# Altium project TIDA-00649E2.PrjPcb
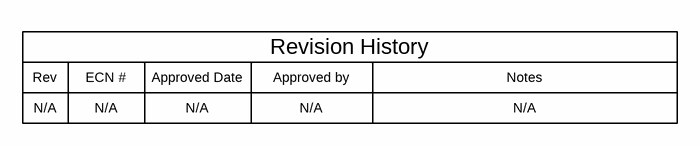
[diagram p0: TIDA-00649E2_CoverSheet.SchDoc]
TID: TIDA-00649; TechSupport: http://www.ti.com/support; SCH_Rev: E2; PRJ_Title: 4-20-mA Loop Energy Harvester Reference Design; PRJ_Number: TIDA-00649; PRJ_Engineer: GVN; PRJ_Customer: Public Release; PCB_Rev: E2; CopyrightYear: 2016
4 sheets, 121 parts. Net scope: flat (ports and power ports of the same name join across sheets).
Board file: TIDA-00649E2_PCB.PcbDoc
Sheets:
  TIDA-00649E2_CoverSheet.SchDoc
  TIDA-00649E2_DiodeVoltage.SchDoc
  TIDA-00649E2_EVM_Hardware.SchDoc
  TIDA-00649E2_Boost.SchDoc

## Sheet TIDA-00649E2_CoverSheet.SchDoc
size 431 x 279 mm; Date: Not shown in title block; ApprovedBy: Not shown in title block; CheckedBy: Not shown in title block; Author: Not shown in title block; CompanyName: Not shown in title block; Engineer: Not shown in title block; Organization: Not shown in title block; Address1: Not shown in title block; Address2: Not shown in title block; Address3: Not shown in title block; Address4: Not shown in title block; DocumentNumber: 1; Revision: E2; SheetNumber: 1; SheetTotal: 4; PageSetup: Record=PageOptions¦CenterHorizontal=True¦CenterVertical=True¦PrintScale=1.00¦XCorrection=1.00¦YCorrection=1.00¦PrintKind=0¦BorderSize=5000000¦LeftOffset=0¦BottomOffset=0¦Orientation=2¦PaperLength=1000¦PaperWidth=1000¦Scale=100¦PaperSource=15¦PrintQuality=600¦MediaType=1¦DitherType=10¦PaperKind=Letter¦PrintScaleMode=1

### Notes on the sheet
- Rev
- N/A
- ECN #
- Approved Date
- Approved by
- Revision History
- Notes

## Sheet TIDA-00649E2_DiodeVoltage.SchDoc: Diode Voltage
size 431 x 279 mm; Date: Not shown in title block; ApprovedBy: Not shown in title block; CheckedBy: Not shown in title block; Author: Not shown in title block; CompanyName: Not shown in title block; Engineer: Not shown in title block; Organization: Not shown in title block; Address1: Not shown in title block; Address2: Not shown in title block; Address3: Not shown in title block; Address4: Not shown in title block; DocumentNumber: 2; Revision: E2; SheetNumber: 2; SheetTotal: 4; PageSetup: Record=PageOptions¦CenterHorizontal=True¦CenterVertical=True¦PrintScale=0.95¦XCorrection=1.00¦YCorrection=1.00¦PrintKind=0¦BorderSize=5000000¦LeftOffset=0¦BottomOffset=0¦Orientation=2¦PaperLength=1000¦PaperWidth=1000¦Scale=100¦PaperSource=15¦PrintQuality=-3¦MediaType=1¦DitherType=10¦PrintScaleMode=1¦PaperKind=11x17¦PaperIndex=3
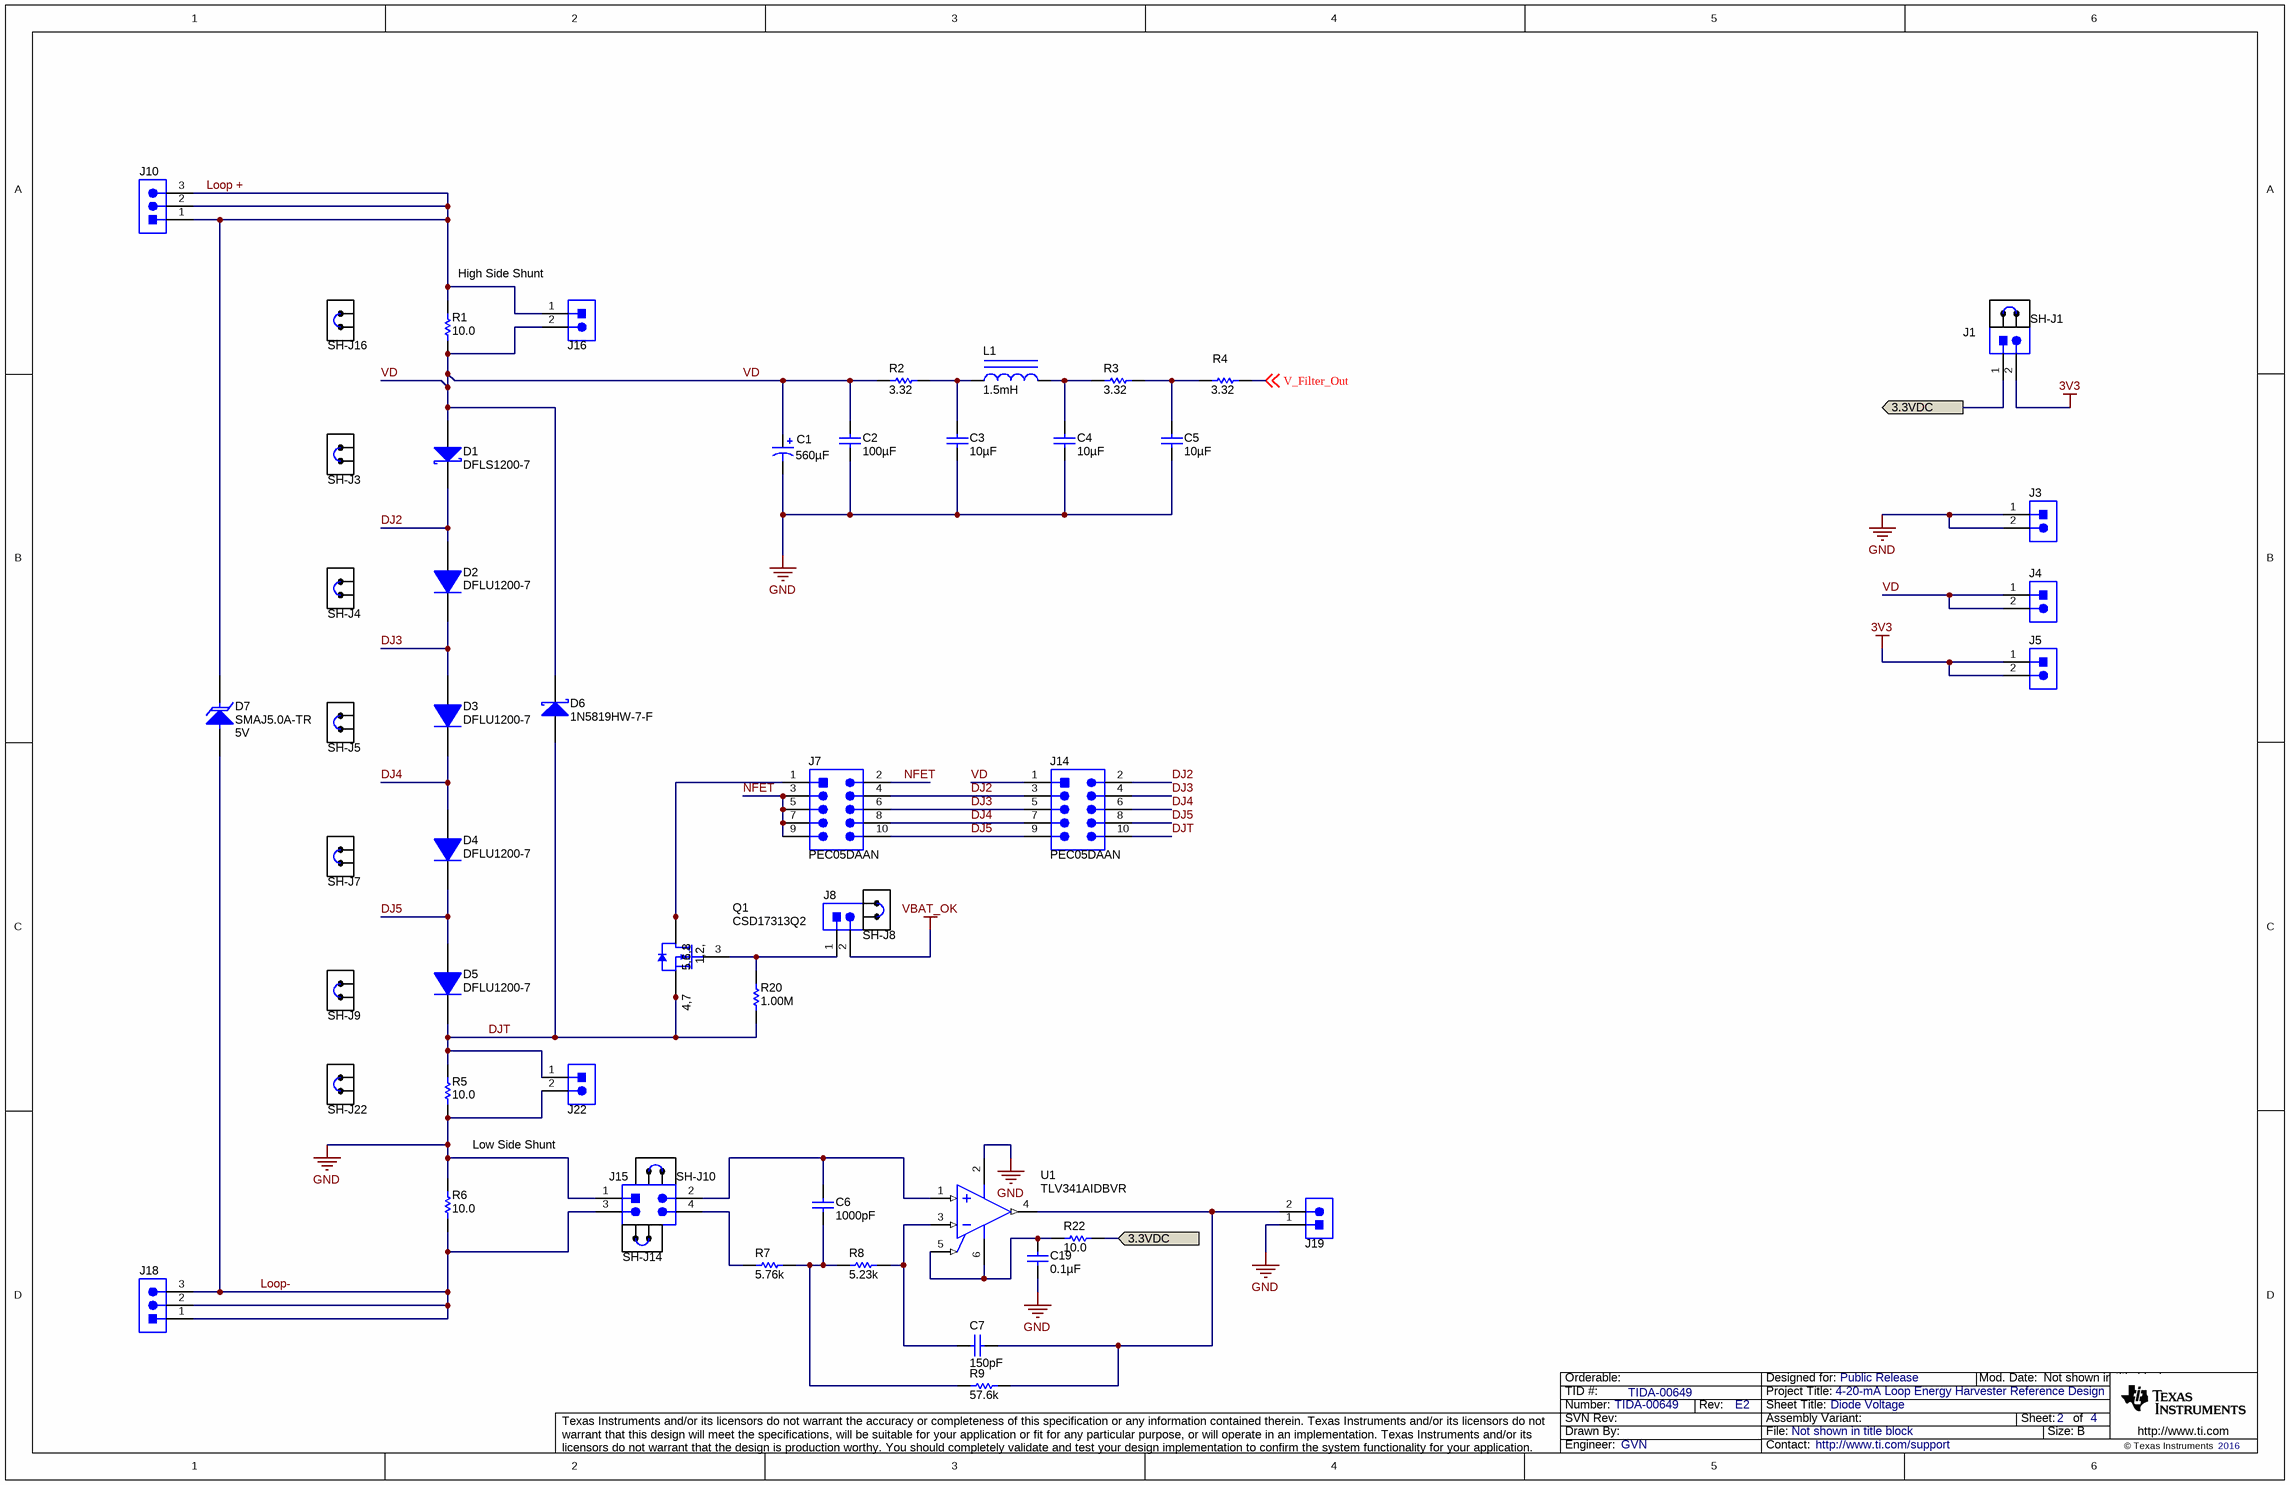
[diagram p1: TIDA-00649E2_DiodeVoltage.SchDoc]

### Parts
C1  ValueDisplayed: 560µF  [Panasonic_G]  (hidden comment: EEEFPE561UAP)
C2  ValueDisplayed: 100µF  [0805_HV]  (hidden comment: GRM21BR60J107M)
C3  ValueDisplayed: 10µF  [0805_HV]  (hidden comment: GRM21BR61A106KE19L)
C4  ValueDisplayed: 10µF  [0805_HV]  (hidden comment: GRM21BR61A106KE19L)
C5  ValueDisplayed: 10µF  [0805_HV]  (hidden comment: GRM21BR61A106KE19L)
C6  ValueDisplayed: 1000pF  [0603]  (hidden comment: C0603C102J5GAC)
C7  ValueDisplayed: 150pF  [0603]  (hidden comment: C0603C151J5GACTU)
C19  ValueDisplayed: 0.1µF  [0603]  (hidden comment: 885012206046)
D1  DFLS1200-7  [PowerDI123]
D2  DFLU1200-7  [PowerDI123]
D3  DFLU1200-7  [PowerDI123]
D4  DFLU1200-7  [PowerDI123]
D5  DFLU1200-7  [PowerDI123]
D6  1N5819HW-7-F  [SOD-123]
D7  SMAJ5.0A-TR  value 5V  [SMA]
J1  61300211121  [WURTH_61300211121]  (value not drawn)
J3  SSW-102-01-T-S  [Samtec_SSW-102-01-x-S]  (value not drawn)
J4  SSW-102-01-T-S  [Samtec_SSW-102-01-x-S]  (value not drawn)
J5  SSW-102-01-T-S  [Samtec_SSW-102-01-x-S]  (value not drawn)
J7  PEC05DAAN  [CONN_PEC05DAAN]
J8  61300211121  [WURTH_61300211121]  (value not drawn)
J10  61300311121  [WURTH_61300311121]  (value not drawn)
J14  PEC05DAAN  [CONN_PEC05DAAN]
J15  PBC02DAAN  [Sullins_PxC02DAAN]  (value not drawn)
J16  61300211121  [WURTH_61300211121]  (value not drawn)
J18  61300311121  [WURTH_61300311121]  (value not drawn)
J19  61300211121  [WURTH_61300211121]  (value not drawn)
J22  61300211121  [WURTH_61300211121]  (value not drawn)
L1  ValueDisplayed: 1.5mH  [SLF10145]  (hidden comment: SLF10145T-152MR22-PF)
Q1  CSD17313Q2  [DQK0006C]
R1  ValueDisplayed: 10.0  [1206]  (hidden comment: CRCW120610R0FKEA)
R2  ValueDisplayed: 3.32  [0402]  (hidden comment: CRCW04023R32FKED)
R3  ValueDisplayed: 3.32  [0402]  (hidden comment: CRCW04023R32FKED)
R4  ValueDisplayed: 3.32  [0402]  (hidden comment: CRCW04023R32FKED)
R5  ValueDisplayed: 10.0  [1206]  (hidden comment: CRCW120610R0FKEA)
R6  ValueDisplayed: 10.0  [1206]  (hidden comment: CRCW120610R0FKEA)
R7  ValueDisplayed: 5.76k  [0603]  (hidden comment: RC0603FR-075K76L)
R8  ValueDisplayed: 5.23k  [0603]  (hidden comment: CRCW06035K23FKEA)
R9  ValueDisplayed: 57.6k  [0603]  (hidden comment: CRCW060357K6FKEA)
R20  ValueDisplayed: 1.00M  [0603]  (hidden comment: CRCW06031M00FKEA)
R22  ValueDisplayed: 10.0  [0603]  (hidden comment: CRCW060310R0FKEA)
SH-J1  60900213421  [Wurth_60900213421]  (value not drawn)
SH-J3  60900213421  [Wurth_60900213421]  (value not drawn)
SH-J4  60900213421  [Wurth_60900213421]  (value not drawn)
SH-J5  60900213421  [Wurth_60900213421]  (value not drawn)
SH-J7  60900213421  [Wurth_60900213421]  (value not drawn)
SH-J8  60900213421  [Wurth_60900213421]  (value not drawn)
SH-J9  60900213421  [Wurth_60900213421]  (value not drawn)
SH-J10  60900213421  [Wurth_60900213421]  (value not drawn)
SH-J14  60900213421  [Wurth_60900213421]  (value not drawn)
SH-J16  60900213421  [Wurth_60900213421]  (value not drawn)
SH-J22  60900213421  [Wurth_60900213421]  (value not drawn)
U1  TLV341AIDBVR  [DBV0006A_N]

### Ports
3.3VDC

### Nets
3V3: J1.2 J5.1 J5.2
GND: C1.2(-) C2.2 C3.2 C4.2 C5.2 C19.1 J3.1 J3.2 J15.1 J19.1 J22.2 R5.1 R6.2 U1.2(GND)
VBAT_OK: J8.2
3.3VDC: J1.1 R22.2 ; port 3.3VDC
DJ2: D1.1(K) D2.2(A) J7.4 J14.2 J14.3
DJ3: D2.1(K) D3.2(A) J7.6 J14.4 J14.5
DJ4: D3.1(K) D4.2(A) J7.8 J14.6 J14.7
DJ5: D4.1(K) D5.2(A) J7.10 J14.8 J14.9
DJT: D5.1(K) D6.2(A) J14.10 J22.1 Q1.4(S) Q1.7(S) R5.2 R20.1
Loop +: D7.1(K) J10.1 J10.2 J10.3 J16.1 R1.2
Loop-: D7.2(A) J15.3 J18.1 J18.2 J18.3 R6.1
NFET: J7.2 J7.3 J7.5 J7.7 J7.9
V_Filter_Out: R4.2 ; off-sheet V_Filter_Out
VD: C1.1(+) C2.1 D1.2(A) D6.1(K) J4.1 J4.2 J14.1 J16.2 R1.1 R2.1
NetC3_1: C3.1 L1.1 R2.2
NetC4_1: C4.1 L1.2 R3.1
NetC5_1: C5.1 R3.2 R4.1
NetC6_1: C6.1 J15.2 U1.1(IN+)
NetC6_2: C6.2 R7.2 R8.1 R9.1
NetC7_1: C7.1 J19.2 R9.2 U1.4(OUT)
NetC7_2: C7.2 R8.2 U1.3(IN-)
NetC19_2: C19.2 R22.1 U1.5(~{SHDN}) U1.6(V+)
NetJ7_1: J7.1 Q1.1(D) Q1.2(D) Q1.5(D) Q1.6(D) Q1.8(D)
NetJ8_1: J8.1 Q1.3(G) R20.2
NetJ15_4: J15.4 R7.1

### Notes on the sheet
- High Side Shunt
- Low Side Shunt

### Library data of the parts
C1 = EEEFPE561UAP: CAP, AL, 560 µF, 25 V, +/- 20%, 0.08 ohm, AEC-Q200 Grade 2, SMD; Manufacturer: Panasonic; Polarized: Y; CompType: Capacitor; Value: 560uF; U/M: EA; Cap_F: 0.00056; Tolerance_%: 20; VDC_V: 25; Value2: 25V; ESR_ohm: 0.08; IRMS_A: 0.85; TaMin_C: -55; TaMax_C: 105; Cap_Case: 10x10.2mm; SizeAreaWB_mm2: 151.29; SizeArea_mm2: 106.09; SizeX_mm: 10.3; SizeZ_mm: 10.5; AEC Category: Q200; AEC Grade: 2
C2 = GRM21BR60J107M: CAP, CERM, 100 µF, 6.3 V, +/- 20%, X5R, 0805; Manufacturer: MuRata; Polarized: N; CompType: Capacitor; Value: 100uF; U/M: EA; Cap_F: 0.0001; Tolerance_%: 20; Value1: Unknown; VDC_V: 6.3; Value2: 6.3V; TaMin_C: -55; TaMax_C: 85; Cap_Case: 0805; SizeArea_mm2: 2.5; SizeAreaWB_mm2: 6.75; SizeX_mm: 2; SizeY_mm: 1.25; SizeZ_mm: 1.45; AEC Category: Q200
C3-C5 = GRM21BR61A106KE19L: CAP, CERM, 10 µF, 10 V, +/- 10%, X5R, 0805; Manufacturer: MuRata; Polarized: N; CompType: Capacitor; Value: 10uF; U/M: EA; Cap_F: 0.00001; Tolerance_%: 10; ESR_ohm: 0.002; Value1: 0.002 ohm; Value2: 10V; TaMin_C: -55; TaMax_C: 85; Cap_Case: 0805; SizeArea_mm2: 2.5; SizeAreaWB_mm2: 6.75; SizeX_mm: 2; SizeY_mm: 1.25; SizeZ_mm: 1.45; AEC Category: Q200
C6 = C0603C102J5GAC: CAP, CERM, 1000 pF, 50 V, +/- 5%, C0G/NP0, 0603; Manufacturer: Kemet; Polarized: N; CompType: Capacitor; Value: 1000pF; U/M: EA; Cap_F: 0.000000001; Tolerance_%: 5; Value1: Unknown; VDC_V: 50; Value2: 50V; TaMin_C: -55; TaMax_C: 125; SizeArea_mm2: 1.28; SizeAreaWB_mm2: 4.68; SizeX_mm: 1.6; SizeY_mm: 0.8; SizeZ_mm: 1; AEC Category: Q200
C7 = C0603C151J5GACTU: CAP, CERM, 150 pF, 50 V, +/- 5%, C0G/NP0, 0603; Manufacturer: Kemet; Polarized: N; CompType: Capacitor; Value: 150pF; U/M: EA; Cap_F: 0.00000000015; Tolerance_%: 5; Value1: Unknown; VDC_V: 50; Value2: 50V; TaMin_C: -55; TaMax_C: 125; SizeArea_mm2: 1.28; SizeAreaWB_mm2: 4.68; SizeX_mm: 1.6; SizeY_mm: 0.8; SizeZ_mm: 1; AEC Category: Q200
C19 = 885012206046: CAP, CERM, 0.1 µF, 16 V, +/- 10%, X7R, 0603; Manufacturer: Wurth Elektronik; Polarized: N; CompType: Capacitor; Value: 0.1uF; U/M: EA; Cap_F: 0.0000001; Tolerance_%: 10; Value1: Unknown; VDC_V: 16; Value2: 16V; TaMin_C: -55; TaMax_C: 125; SizeArea_mm2: 1.28; SizeAreaWB_mm2: 4.68; SizeX_mm: 1.6; SizeY_mm: 0.8; SizeZ_mm: 1; AEC Category: Q200
D1 = DFLS1200-7: Diode, Schottky, 200 V, 1 A, PowerDI123; Manufacturer: Diodes Inc.; U/M: EA; Vf_V: 0.85; Value: 200V; Value1: 1A; Value2: 0.85V; Io_A: 1; Vr_V: 200; TJmax_C: 175; RJC_CperW: 7; SizeAreaWB_mm2: 13.066; SizeArea_mm2: 6.586; SizeX_mm: 3.7; SizeY_mm: 1.78; SizeZ_mm: 0.98; AEC Category: Q101
D2-D5 = DFLU1200-7: Diode, Superfast Rectifier, 200 V, 1 A, AEC-Q101, PowerDI123; Manufacturer: Diodes Inc.; U/M: EA; Vf_V: 0.98; Value: 200V; Value1: 1A; Value2: 0.98V; Io_A: 1; Vr_V: 200; TJmax_C: 150; SizeAreaWB_mm2: 13.066; SizeArea_mm2: 6.586; SizeX_mm: 3.7; SizeY_mm: 1.78; AEC Category: Q101; AEC Qualified: Y
D6 = 1N5819HW-7-F: Diode, Schottky, 40 V, 1 A, SOD-123; Manufacturer: Diodes Inc.; U/M: EA; Vf_V: 0.45; Value: 40V; Value1: 1A; Value2: 0.45V; Io_A: 1; Vr_V: 40; TJmax_C: 125; SizeAreaWB_mm2: 13.095; SizeArea_mm2: 6.545; SizeX_mm: 3.85; SizeY_mm: 1.7; SizeZ_mm: 1.35; AEC Category: Q101
D7 = SMAJ5.0A-TR: Diode, TVS, Uni, 5 V, 13.4 Vc, SMA; Manufacturer: STMicroelectronics; U/M: EA; Vr_V: 5; Value1: W; RJA_CperW: 120; SizeAreaWB_mm2: 37.3428; SizeArea_mm2: 16.3228; SizeX_mm: 5.59; SizeY_mm: 2.92; SizeZ_mm: 2.87; AEC Category: Q101; AEC Qualified: N
J1 J8 J16 J19 J22 = 61300211121: Header, 2.54 mm, 2x1, Gold, TH; Manufacturer: Wurth Elektronik; SymbolCreator: a0412235
J3-J5 = SSW-102-01-T-S: Receptacle, 2x1, 2.54mm, Tin, TH; Manufacturer: Samtec; SymbolCreator: a0412235; Pitch_mm: 2.54; Gender: Female; Row_Count: 1; Current_A: 5.7; Cert_CSA: Y
J7 J14 = PEC05DAAN: Header, 100mil, 5x2, Tin, TH; Manufacturer: Sullins Connector Solutions; SymbolCreator: a0412235; Pitch_mm: 2.54; Gender: Male; Shrouded: N; Row_Count: 2; Current_A: 3; Voltage_V: 1800; Cert_UL: Y
J10 J18 = 61300311121: Header, 2.54 mm, 3x1, Gold, TH; Manufacturer: Wurth Elektronik; SymbolCreator: a0799628
J15 = PBC02DAAN: Header, 2.54mm, 2x2, Gold, TH; Manufacturer: Sullins Connector Solutions; SymbolCreator: a0412235; Pitch_mm: 2.54; Gender: Male; Shrouded: N; Row_Count: 2; Current_A: 3; Voltage_V: 1800; Cert_UL: Y
L1 = SLF10145T-152MR22-PF: Inductor, Shielded Drum Core, Ferrite, 1.5 mH, 0.22 A, 3.4 ohm, SMD; Manufacturer: TDK; Value: 1.5mH; Ind_H: 1.5E-3; Imax_A: 0.22; Irms: 0.26A @ 30C rise; Isat: 0.22A @ 10% inductance drop; DCR_ohm: 3.4; Value1: 3.4 ohm; Value2: 0.22A; AEC Category: Q200
Q1 = CSD17313Q2: MOSFET, N-CH, 30 V, 5 A, DQK0006C (WSON-6); Manufacturer: Texas Instruments; Alternate Manufacturer: None; U/M: EA; ChType: N; Value: 30V; VdsMax_V: 30; Value1: 0.026 ohm; Rdson45_ohm: 0.026; Value2: 2.1 nC; QgTyp_nC: 2.1; Vgs_V: 10; IdsMax_A: 5; SizeAreaWB_mm2: 9; SizeArea_mm2: 4; SizeX_mm: 2; SizeZ_mm: 0.8; AEC Category: Q101
R1 R5 R6 = CRCW120610R0FKEA: RES, 10.0, 1%, 0.25 W, 1206; Manufacturer: Vishay-Dale; CompType: Resistor; Value: 10.0; Res_ohm: 10; Value_Code: 10R0; Tolerance_%: 1; Power_W: 0.25; Value2: 0.25W; VDC_V: 200; TempCo: 100 ppm/C; SizeArea_mm2: 5.12; SizeX_mm: 3.2; SizeY_mm: 1.6; SizeZ_mm: 1.35; EIA_Code: E96; U/M: EA; AEC Category: Q200
R2-R4 = CRCW04023R32FKED: RES, 3.32, 1%, 0.063 W, 0402; Manufacturer: Vishay-Dale; CompType: Resistor; Value: 3.32; Value_Code: 3R32; Tolerance_%: 1; Power_W: 0.063; Value2: 0.063W; VDC_V: 50; TempCo: 100 ppm/C; SizeArea_mm2: 0.5; SizeZ_mm: 0.6; EIA_Code: E96; U/M: EA; AEC Category: Q200
R7 = RC0603FR-075K76L: RES, 5.76 k, 1%, 0.1 W, 0603; Manufacturer: Yageo America; CompType: Resistor; Value: 5.76k; Res_ohm: 5760; Value_Code: 5k76; Tolerance_%: 1; Power_W: 0.1; Value2: 0.1W; VDC_V: 150; TempCo: 200 ppm/C; SizeArea_mm2: 1.28; SizeX_mm: 1.6; SizeY_mm: 0.8; EIA_Code: E96; U/M: EA; AEC Category: Q200
R8 = CRCW06035K23FKEA: RES, 5.23 k, 1%, 0.1 W, 0603; Manufacturer: Vishay-Dale; CompType: Resistor; Value: 5.23k; Res_ohm: 5230; Value_Code: 5k23; Tolerance_%: 1; Power_W: 0.1; Value2: 0.1W; VDC_V: 75; TempCo: 100 ppm/C; SizeArea_mm2: 1.28; SizeX_mm: 1.6; SizeY_mm: 0.8; EIA_Code: E96; U/M: EA; AEC Category: Q200
R9 = CRCW060357K6FKEA: RES, 57.6 k, 1%, 0.1 W, 0603; Manufacturer: Vishay-Dale; CompType: Resistor; Value: 57.6k; Res_ohm: 57600; Value_Code: 57k6; Tolerance_%: 1; Power_W: 0.1; Value2: 0.1W; VDC_V: 75; TempCo: 100 ppm/C; SizeArea_mm2: 1.28; SizeX_mm: 1.6; SizeY_mm: 0.8; EIA_Code: E96; U/M: EA; AEC Category: Q200
R20 = CRCW06031M00FKEA: RES, 1.00 M, 1%, 0.1 W, 0603; Manufacturer: Vishay-Dale; CompType: Resistor; Value: 1.00Meg; Res_ohm: 1000000; Value_Code: 1M00; Tolerance_%: 1; Power_W: 0.1; Value2: 0.1W; VDC_V: 75; TempCo: 100 ppm/C; SizeArea_mm2: 1.28; SizeX_mm: 1.6; SizeY_mm: 0.8; EIA_Code: E96; U/M: EA; AEC Category: Q200
R22 = CRCW060310R0FKEA: RES, 10.0, 1%, 0.1 W, 0603; Manufacturer: Vishay-Dale; CompType: Resistor; Value: 10.0; Res_ohm: 10; Value_Code: 10R0; Tolerance_%: 1; Power_W: 0.1; Value2: 0.1W; VDC_V: 75; TempCo: 100 ppm/C; SizeArea_mm2: 1.28; SizeX_mm: 1.6; SizeY_mm: 0.8; EIA_Code: E96; U/M: EA; AEC Category: Q200
SH-J1 SH-J3-SH-J5 SH-J7-SH-J10 SH-J14 SH-J16 SH-J22 = 60900213421: Shunt, 2.54mm, Gold, Black; Manufacturer: Wurth Elektronik
U1 = TLV341AIDBVR: Low-Voltage, Rail-To-Rail Output CMOS Operational Amplifier with Shutdown, 1.5 to 5.5 V, -40 to 125 degC, 6-pin SOT23 (DBV0006A), Green (RoHS & no Sb/Br); Alternate Manufacturer: Texas Instruments; Alternate PartNumber: Equivalent; CMRR(Min)(dB): 50; GBW(Typ)(MHz): 2.2; IIB(Max)(pA): 3000; Iq per channel(Max)(mA): 0.15; Number of Channels: 1; Offset Drift(Typ)(uV/C): 1.9; Rating: Catalog; Slew Rate(Typ)(V/us): 0.9; Sub Family: General Purpose Amplifier, Low Power Amp (<=500uA), Low Supply Voltage Amplifier (<=2.7V); Total Supply Voltage(Max)(+5V is 5, +/-5V is 10): 5.5; Total Supply Voltage(Min)(+5V is 5, +/-5V is 10): 1.5; Vio (25C)(Max)(mV): 1.25; Vn at 1kHz(Typ)(nV/rtHz): 33

## Sheet TIDA-00649E2_EVM_Hardware.SchDoc
size 431 x 279 mm; Date: Not shown in title block; ApprovedBy: Not shown in title block; CheckedBy: Not shown in title block; Author: Not shown in title block; CompanyName: Not shown in title block; Engineer: Not shown in title block; Organization: Not shown in title block; Address1: Not shown in title block; Address2: Not shown in title block; Address3: Not shown in title block; Address4: Not shown in title block; DocumentNumber: 4; Revision: E2; SheetNumber: 4; SheetTotal: 4; PageSetup: Record=PageOptions¦CenterHorizontal=True¦CenterVertical=True¦PrintScale=1.00¦XCorrection=1.00¦YCorrection=1.00¦PrintKind=0¦BorderSize=5000000¦LeftOffset=0¦BottomOffset=0¦Orientation=2¦PaperLength=1000¦PaperWidth=1000¦Scale=100¦PaperSource=15¦PrintQuality=600¦MediaType=1¦DitherType=10¦PaperKind=Letter¦PrintScaleMode=1
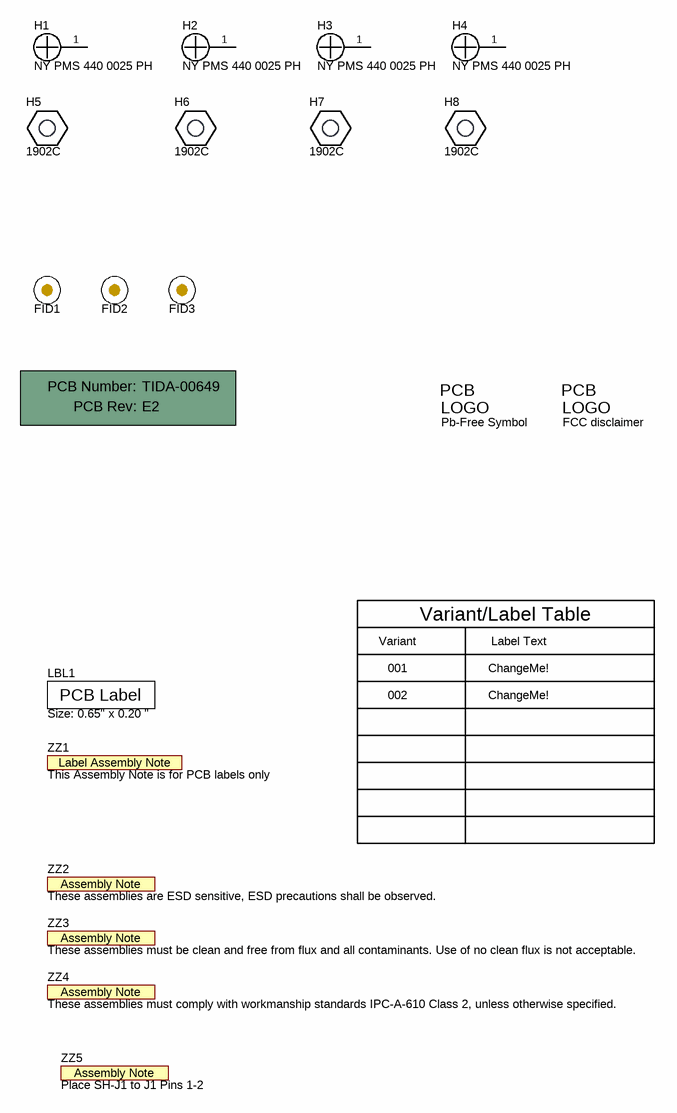
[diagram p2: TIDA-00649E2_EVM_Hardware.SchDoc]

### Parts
!PCB1  Printed Circuit Board  (value not drawn)  (mechanical)
FID1  Fiducial  [Fiducial10-20]  (value not drawn)
FID2  Fiducial  [Fiducial10-20]  (value not drawn)
FID3  Fiducial  [Fiducial10-20]  (value not drawn)
H1  NY PMS 440 0025 PH  [NY PMS 440 0025 PH]
H2  NY PMS 440 0025 PH  [NY PMS 440 0025 PH]
H3  NY PMS 440 0025 PH  [NY PMS 440 0025 PH]
H4  NY PMS 440 0025 PH  [NY PMS 440 0025 PH]
H5  1902C  [Keystone_1902C]
H6  1902C  [Keystone_1902C]
H7  1902C  [Keystone_1902C]
H8  1902C  [Keystone_1902C]
LBL1  Size: 0.65" x 0.20 "  [Label_650x200]
Logo2  Pb-Free Symbol  [Pb-Free_Overlay_Small]  (no BOM)
Logo3  FCC disclaimer  [FCC_disclaimer]  (no BOM)
ZZ1  This Assembly Note is for PCB labels only  [AssemblyNoteLabel]  (no BOM)
ZZ2  These assemblies are ESD sensitive, ESD precautions shall be observed.  [AssemblyNote]  (no BOM)
ZZ3  These assemblies must be clean and free from flux and all contaminants. Use of no clean flux is not acceptable.  [AssemblyNote]  (no BOM)
ZZ4  These assemblies must comply with workmanship standards IPC-A-610 Class 2, unless otherwise specified.  [AssemblyNote]  (no BOM)
ZZ5  Place SH-J1 to J1 Pins 1-2  [AssemblyNote]  (no BOM)

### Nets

Not connected (* = marked no-connect by the designer): H1 1; H2 1; H3 1; H4 1

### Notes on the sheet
- Variant
- Variant/Label Table
- Label Text
- 001
- 002
- ChangeMe!

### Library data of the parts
!PCB1 = PCB: Manufacturer: Any; PartNumber: TIDA-00649; SymbolCreator: a0412235
FID1-FID3 = Fiducial: Fiducial mark.  There is nothing to buy or mount.; SymbolCreator: codlsc
H1-H4 = NY PMS 440 0025 PH: Machine Screw, Round, #4-40 x 1/4, Nylon, Philips panhead; Manufacturer: B&F Fastener Supply; CompType: Hardware; SymbolCreator: codlsc; U/M: EA
H5-H8 = 1902C: Standoff, Hex, 0.5"L #4-40 Nylon; Manufacturer: Keystone; CompType: Hardware
LBL1 = THT-14-423-10: Thermal Transfer Printable Labels, 0.650" W x 0.200" H - 10,000 per roll; Manufacturer: Brady; SymbolCreator: a0412235; CompType: Label
Logo2 = Pb-Free: SymbolCreator: a0412235
Logo3 = FCC_disclaimer: SymbolCreator: codlsc
ZZ1 = AssemblyNoteLabel: SymbolCreator: a0412235
ZZ2-ZZ5 = AssemblyNote: SymbolCreator: codlsc

## Sheet TIDA-00649E2_Boost.SchDoc: Boost Regulator
size 431 x 279 mm; Date: Not shown in title block; ApprovedBy: Not shown in title block; CheckedBy: Not shown in title block; Author: Not shown in title block; CompanyName: Not shown in title block; Engineer: Not shown in title block; Organization: Not shown in title block; Address1: Not shown in title block; Address2: Not shown in title block; Address3: Not shown in title block; Address4: Not shown in title block; DocumentNumber: 3; Revision: E2; SheetNumber: 3; SheetTotal: 4; PageSetup: Record=PageOptions¦CenterHorizontal=True¦CenterVertical=True¦PrintScale=0.95¦XCorrection=1.00¦YCorrection=1.00¦PrintKind=0¦BorderSize=5000000¦LeftOffset=0¦BottomOffset=0¦Orientation=2¦PaperLength=1000¦PaperWidth=1000¦Scale=100¦PaperSource=15¦PrintQuality=-3¦MediaType=1¦DitherType=10¦PrintScaleMode=1¦PaperKind=11x17¦PaperIndex=3
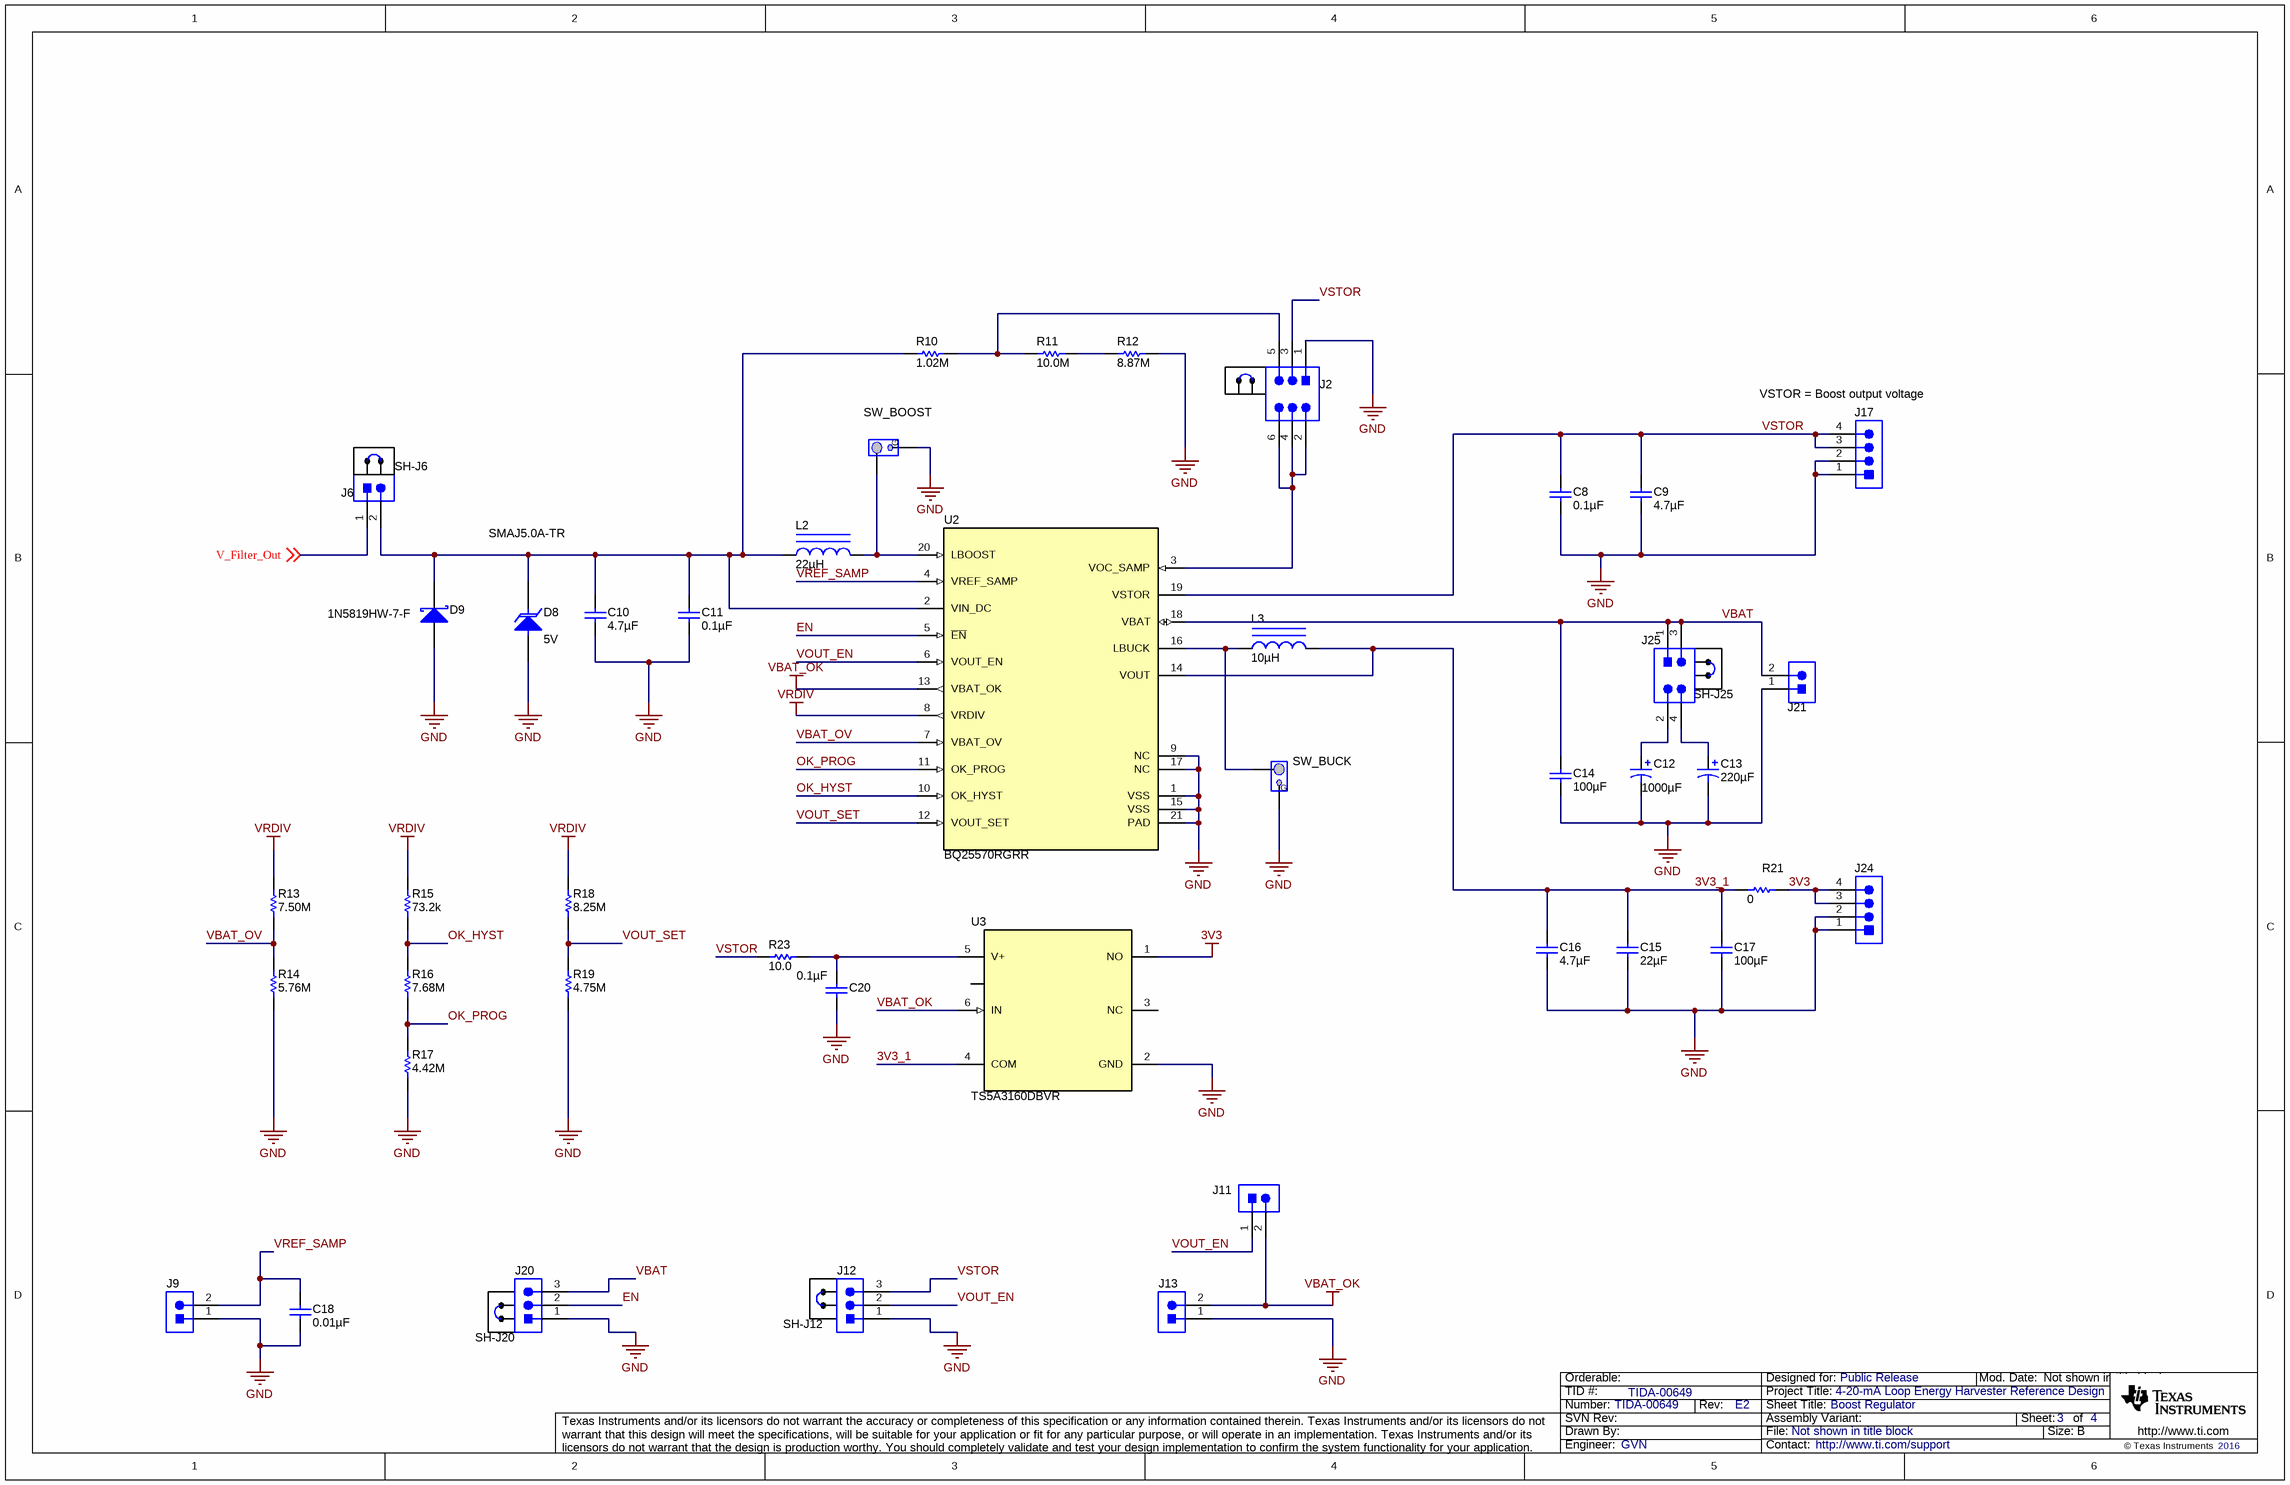
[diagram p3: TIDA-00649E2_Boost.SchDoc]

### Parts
C8  ValueDisplayed: 0.1µF  [0805_HV]  (hidden comment: C0805C104K4RACTU)
C9  ValueDisplayed: 4.7µF  [0805_HV]  (hidden comment: LMK212B7475KG-T)
C10  ValueDisplayed: 4.7µF  [0805_HV]  (hidden comment: C0805C475K8PACTU)
C11  ValueDisplayed: 0.1µF  [0805_HV]  (hidden comment: C0805C104K4RACTU)
C12  ValueDisplayed: 1000µF  [SM_RADIAL_G]  (hidden comment: EEE-FC1A102P)
C13  ValueDisplayed: 220µF  [CAPSMT_62_H70]  (hidden comment: APXE100ARA221MH70G)
C14  ValueDisplayed: 100µF  [1210_280]  (hidden comment: C1210C107M8PACTU)
C15  ValueDisplayed: 22µF  [0805_HV]  (hidden comment: JMK212BJ226MG-T)
C16  ValueDisplayed: 4.7µF  [0805_HV]  (hidden comment: GRM21BR71A475KA73L)
C17  ValueDisplayed: 100µF  [1210_280]  (hidden comment: C1210C107M8PACTU)
C18  ValueDisplayed: 0.01µF  [0603]  (hidden comment: GRM188R71H103KA01D)
C20  ValueDisplayed: 0.1µF  [0603]  (hidden comment: 885012206046)
D8  SMAJ5.0A-TR  value 5V  [SMA]
D9  1N5819HW-7-F  [SOD-123]
J2  61300621121  [Wurth_61300621121]  (value not drawn)
J6  61300211121  [WURTH_61300211121]  (value not drawn)
J9  61300211121  [WURTH_61300211121]  (value not drawn)
J11  61300211121  [WURTH_61300211121]  (value not drawn)
J12  61300311121  [WURTH_61300311121]  (value not drawn)
J13  61300211121  [WURTH_61300211121]  (value not drawn)
J17  61300411121  [WURTH_61300411121]  (value not drawn)
J20  61300311121  [WURTH_61300311121]  (value not drawn)
J21  61300211121  [WURTH_61300211121]  (value not drawn)
J24  61300411121  [WURTH_61300411121]  (value not drawn)
J25  PBC02DAAN  [Sullins_PxC02DAAN]  (value not drawn)
L2  ValueDisplayed: 22µH  [WE-TPC-S]  (hidden comment: 744031220)
L3  ValueDisplayed: 10µH  [WE-TPC_2813]  (hidden comment: 744029100)
R10  ValueDisplayed: 1.02M  [0603S]  (hidden comment: CRCW06031M02FKEA)
R11  ValueDisplayed: 10.0M  [0603]  (hidden comment: CRCW060310M0FKEA)
R12  ValueDisplayed: 8.87M  [0603]  (hidden comment: CRCW06038M87FKEA)
R13  ValueDisplayed: 7.50M  [0603]  (hidden comment: CRCW06037M50FKEA)
R14  ValueDisplayed: 5.76M  [0603]  (hidden comment: CRCW06035M76FKEA)
R15  ValueDisplayed: 73.2k  [0603]  (hidden comment: CRCW060373K2FKEA)
R16  ValueDisplayed: 7.68M  [0603]  (hidden comment: CRCW06037M68FKEA)
R17  ValueDisplayed: 4.42M  [0603]  (hidden comment: CRCW06034M42FKEA)
R18  ValueDisplayed: 8.25M  [0603]  (hidden comment: CRCW06038M25FKEA)
R19  ValueDisplayed: 4.75M  [0603]  (hidden comment: CRCW06034M75FKEA)
R21  ValueDisplayed: 0  [0603]  (hidden comment: MCR03EZPJ000)
R23  ValueDisplayed: 10.0  [0603]  (hidden comment: CRCW060310R0FKEA)
SH-J2  60900213421  [Wurth_60900213421]  (value not drawn)
SH-J6  60900213421  [Wurth_60900213421]  (value not drawn)
SH-J12  60900213421  [Wurth_60900213421]  (value not drawn)
SH-J20  60900213421  [Wurth_60900213421]  (value not drawn)
SH-J25  60900213421  [Wurth_60900213421]  (value not drawn)
SW_BOOST  TESTPOINT_PIGTAIL  [TESTPOINT_PIGTAIL]  (value not drawn)  (no BOM)
SW_BUCK  TESTPOINT_PIGTAIL  [TESTPOINT_PIGTAIL]  (value not drawn)  (no BOM)
U2  BQ25570RGRR  [RGR0020A]
U3  TS5A3160DBVR  [DBV0006A_N]

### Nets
3V3: J24.3 J24.4 R21.2 U3.1(NO)
GND: C8.2 C9.2 C10.2 C11.2 C12.2(-) C13.2(-) C14.1 C15.2 C16.2 C17.1 C18.2 C20.2 D8.2(A) D9.2(A) J2.1 J9.1 J12.1 J13.1 J17.1 J17.2 J20.1 J21.1 J24.1 J24.2 R12.2 R14.2 R17.1 R19.1 SW_BOOST.2 SW_BUCK.2 U2.1(VSS) U2.9(NC) U2.15(VSS) U2.17(NC) U2.21(PAD) U3.2(GND)
VBAT_OK: J11.2 J13.2 U2.13(VBAT_OK) U3.6(IN)
VRDIV: R13.1 R15.2 R18.2 U2.8(VRDIV)
3V3_1: C15.1 C16.1 C17.2 L3.2 R21.1 U2.14(VOUT) U3.4(COM)
EN: J20.2 U2.5(~{EN})
OK_HYST: R15.1 R16.2 U2.10(OK_HYST)
OK_PROG: R16.1 R17.2 U2.11(OK_PROG)
V_Filter_Out: J6.1 ; off-sheet V_Filter_Out
VBAT: C14.2 J20.3 J21.2 J25.1 J25.3 U2.18(VBAT)
VBAT_OV: R13.2 R14.1 U2.7(VBAT_OV)
VOUT_EN: J11.1 J12.2 U2.6(VOUT_EN)
VOUT_SET: R18.1 R19.2 U2.12(VOUT_SET)
VREF_SAMP: C18.1 J9.2 U2.4(VREF_SAMP)
VSTOR: C8.1 C9.1 J2.3 J12.3 J17.3 J17.4 R23.1 U2.19(VSTOR)
NetC10_1: C10.1 C11.1 D8.1(K) D9.1(K) J6.2 L2.1 R10.1 U2.2(VIN_DC)
NetC12_1: C12.1(+) J25.2
NetC13_1: C13.1(+) J25.4
NetC20_1: C20.1 R23.2 U3.5(V+)
NetJ2_2: J2.2 J2.4 J2.6 U2.3(VOC_SAMP)
NetJ2_5: J2.5 R10.2 R11.2
NetL2_2: L2.2 SW_BOOST.1 U2.20(LBOOST)
NetL3_1: L3.1 SW_BUCK.1 U2.16(LBUCK)
NetR11_1: R11.1 R12.1

Not connected (* = marked no-connect by the designer): U3 3(NC)

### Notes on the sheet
- (near J17) VSTOR = Boost output voltage

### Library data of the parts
C8 C11 = C0805C104K4RACTU: CAP, CERM, 0.1 µF, 16 V, +/- 10%, X7R, 0805; Manufacturer: Kemet; Polarized: N; CompType: Capacitor; Value: 0.1uF; U/M: EA; Cap_F: 0.0000001; Tolerance_%: 10; ESR_ohm: 0.064; Value1: 0.064 ohm; VDC_V: 16; Value2: 16V; IRMS_A: 1.64; TaMin_C: -55; TaMax_C: 125; Cap_Case: 0805; SizeArea_mm2: 2.5; SizeAreaWB_mm2: 6.75; SizeX_mm: 2; SizeY_mm: 1.25; SizeZ_mm: 1.45; AEC Category: Q200
C9 = LMK212B7475KG-T: CAP, CERM, 4.7 µF, 10 V, +/- 10%, X7R, 0805; Manufacturer: Taiyo Yuden; Polarized: N; CompType: Capacitor; Value: 4.7uF; U/M: EA; Cap_F: 0.0000047; Tolerance_%: 10; Value1: Unknown; Value2: 10V; TaMin_C: -55; TaMax_C: 125; Cap_Case: 0805; SizeArea_mm2: 2.5; SizeAreaWB_mm2: 6.75; SizeX_mm: 2; SizeY_mm: 1.25; SizeZ_mm: 1.45; AEC Category: Q200
C10 = C0805C475K8PACTU: CAP, CERM, 4.7 µF, 10 V, +/- 10%, X5R, 0805; Manufacturer: Kemet; Polarized: N; CompType: Capacitor; Value: 4.7uF; U/M: EA; Cap_F: 0.0000047; Tolerance_%: 10; ESR_ohm: 0.004; Value1: 0.004 ohm; Value2: 10V; IRMS_A: 9.89; TaMin_C: -55; TaMax_C: 85; Cap_Case: 0805; SizeArea_mm2: 2.5; SizeAreaWB_mm2: 6.75; SizeX_mm: 2; SizeY_mm: 1.25; SizeZ_mm: 1.45; AEC Category: Q200
C12 = EEE-FC1A102P: CAP, AL, 1000 µF, 10 V, +/- 20%, 0.15 ohm, SMD; Manufacturer: Panasonic; Polarized: Y; CompType: Capacitor; Value: 1000uF; U/M: EA; Cap_F: 0.001; Tolerance_%: 20; VDC_V: 10; Value2: 10V; ESR_ohm: 0.15; IRMS_A: 0.67; TaMin_C: -40; TaMax_C: 105; Cap_Case: G; SizeAreaWB_mm2: 172.2; SizeArea_mm2: 123.6; SizeX_mm: 12; SizeY_mm: 10.3; SizeZ_mm: 10.2; AEC Category: Q200
C13 = APXE100ARA221MH70G: CAP, AL, 220 µF, 10 V, +/- 20%, 0.021 ohm, SMD; Manufacturer: Chemi-Con; Polarized: Y; CompType: Capacitor; Value: 220uF; U/M: EA; Cap_F: 0.00022; Tolerance_%: 20; VDC_V: 10; Value2: 10V; ESR_ohm: 0.021; IRMS_A: 3.22; TaMin_C: -55; TaMax_C: 105; Cap_Case: H70; SizeAreaWB_mm2: 110.25; SizeArea_mm2: 72.25; SizeX_mm: 8.5; SizeZ_mm: 7; AEC Category: Q200
C14 C17 = C1210C107M8PACTU: CAP, CERM, 100 µF, 10 V, +/- 20%, X5R, 1210; Manufacturer: Wurth Elektronik; Polarized: N; CompType: Capacitor; Value: 100uF; U/M: EA; Cap_F: 0.0001; Tolerance_%: 20; Value1: Unknown; VDC_V: 10; Value2: 10V; TaMin_C: -55; TaMax_C: 85; Cap_Case: 1210; SizeArea_mm2: 8; SizeAreaWB_mm2: 14.7; SizeX_mm: 3.2; SizeY_mm: 2.5; SizeZ_mm: 2.8; AEC Category: Q200
C15 = JMK212BJ226MG-T: CAP, CERM, 22 µF, 6.3 V, +/- 20%, X5R, 0805; Manufacturer: Taiyo Yuden; Polarized: N; CompType: Capacitor; Value: 22uF; U/M: EA; Cap_F: 0.000022; Tolerance_%: 20; Value1: Unknown; VDC_V: 6.3; Value2: 6.3V; TaMin_C: -55; TaMax_C: 85; Cap_Case: 0805; SizeArea_mm2: 2.5; SizeAreaWB_mm2: 6.75; SizeX_mm: 2; SizeY_mm: 1.25; SizeZ_mm: 1.45; AEC Category: Q200
C16 = GRM21BR71A475KA73L: CAP, CERM, 4.7 µF, 10 V, +/- 10%, X7R, 0805; Manufacturer: MuRata; Polarized: N; CompType: Capacitor; Value: 4.7uF; U/M: EA; Cap_F: 0.0000047; Tolerance_%: 10; Value1: Unknown; Value2: 10V; TaMin_C: -55; TaMax_C: 125; Cap_Case: 0805; SizeArea_mm2: 2.5; SizeAreaWB_mm2: 6.75; SizeX_mm: 2; SizeY_mm: 1.25; SizeZ_mm: 1.45; AEC Category: Q200
C18 = GRM188R71H103KA01D: CAP, CERM, 0.01 µF, 50 V, +/- 10%, X7R, 0603; Manufacturer: MuRata; Polarized: N; CompType: Capacitor; Value: 0.01uF; U/M: EA; Cap_F: 0.00000001; Tolerance_%: 10; Value1: Unknown; VDC_V: 50; Value2: 50V; TaMin_C: -55; TaMax_C: 125; SizeArea_mm2: 1.28; SizeAreaWB_mm2: 4.68; SizeX_mm: 1.6; SizeY_mm: 0.8; SizeZ_mm: 1; AEC Category: Q200
C20 = 885012206046: as C19 on sheet TIDA-00649E2_DiodeVoltage
D8 = SMAJ5.0A-TR: as D7 on sheet TIDA-00649E2_DiodeVoltage
D9 = 1N5819HW-7-F: as D6 on sheet TIDA-00649E2_DiodeVoltage
J2 = 61300621121: Header, 2.54mm, 3x2, Gold, TH; Manufacturer: Wurth Elektronik; SymbolCreator: a0412235; Pitch_mm: 2.54; Gender: Male; Shrouded: N; Row_Count: 2
J6 J9 J11 J13 J21 = 61300211121: as J1 on sheet TIDA-00649E2_DiodeVoltage
J12 J20 = 61300311121: as J10 on sheet TIDA-00649E2_DiodeVoltage
J17 J24 = 61300411121: Header, 2.54 mm, 4x1, Gold, TH; Manufacturer: Wurth Elektronik; SymbolCreator: a0412235
J25 = PBC02DAAN: as J15 on sheet TIDA-00649E2_DiodeVoltage
L2 = 744031220: Inductor, Shielded Drum Core, Ferrite, 22 µH, 0.36 A, 0.41 ohm, SMD; Manufacturer: Wurth Elektronik; Value: 22uH; Ind_H: 22.0E-6; Imax_A: 0.36; Irms: 0.51A @ 30C rise; Isat: 0.36A @ 35% inductance drop; DCR_ohm: 0.41; Value2: 0.36A; SizeAreaWB_mm2: 23.04; SizeArea_mm2: 14.44; SizeX_mm: 3.8; SizeZ_mm: 1.65; AEC Category: Q200
L3 = 744029100: Inductor, Shielded Drum Core, Ferrite, 10 µH, 0.5 A, 0.39 ohm, SMD; Manufacturer: Wurth Elektronik; Value: 10uH; Ind_H: 10.0E-6; Imax_A: 0.5; Irms: 0.75A @ 40C rise; Isat: 0.5A @ 35% inductance drop; DCR_ohm: 0.39; Value2: 0.5A; AEC Category: Q200
R10 = CRCW06031M02FKEA: RES, 1.02 M, 1%, 0.1 W, 0603; Manufacturer: Vishay-Dale; CompType: Resistor; Value: 1.02Meg; Res_ohm: 1020000; Value_Code: 1M02; Tolerance_%: 1; Power_W: 0.1; Value2: 0.1W; VDC_V: 75; TempCo: 100 ppm/C; SizeArea_mm2: 1.28; SizeX_mm: 1.6; SizeY_mm: 0.8; EIA_Code: E96; U/M: EA; AEC Category: Q200
R11 = CRCW060310M0FKEA: RES, 10.0 M, 1%, 0.1 W, 0603; Manufacturer: Vishay-Dale; CompType: Resistor; Value: 10.0Meg; Res_ohm: 10000000; Value_Code: 10M0; Tolerance_%: 1; Power_W: 0.1; Value2: 0.1W; VDC_V: 75; TempCo: 100 ppm/C; SizeArea_mm2: 1.28; SizeX_mm: 1.6; SizeY_mm: 0.8; EIA_Code: E96; U/M: EA; AEC Category: Q200
R12 = CRCW06038M87FKEA: RES, 8.87 M, 1%, 0.1 W, 0603; Manufacturer: Vishay-Dale; CompType: Resistor; Value: 8.87Meg; Res_ohm: 8870000; Value_Code: 8M87; Tolerance_%: 1; Power_W: 0.1; Value2: 0.1W; VDC_V: 75; TempCo: 100 ppm/C; SizeArea_mm2: 1.28; SizeX_mm: 1.6; SizeY_mm: 0.8; EIA_Code: E96; U/M: EA; AEC Category: Q200
R13 = CRCW06037M50FKEA: RES, 7.50 M, 1%, 0.1 W, 0603; Manufacturer: Vishay-Dale; CompType: Resistor; Value: 7.50Meg; Res_ohm: 7500000; Value_Code: 7M50; Tolerance_%: 1; Power_W: 0.1; Value2: 0.1W; VDC_V: 75; TempCo: 100 ppm/C; SizeArea_mm2: 1.28; SizeX_mm: 1.6; SizeY_mm: 0.8; EIA_Code: E96; U/M: EA; AEC Category: Q200
R14 = CRCW06035M76FKEA: RES, 5.76 M, 1%, 0.1 W, 0603; Manufacturer: Vishay-Dale; CompType: Resistor; Value: 5.76Meg; Res_ohm: 5760000; Value_Code: 5M76; Tolerance_%: 1; Power_W: 0.1; Value2: 0.1W; VDC_V: 75; TempCo: 100 ppm/C; SizeArea_mm2: 1.28; SizeX_mm: 1.6; SizeY_mm: 0.8; EIA_Code: E96; U/M: EA; AEC Category: Q200
R15 = CRCW060373K2FKEA: RES, 73.2 k, 1%, 0.1 W, 0603; Manufacturer: Vishay-Dale; CompType: Resistor; Value: 73.2k; Res_ohm: 73200; Value_Code: 73k2; Tolerance_%: 1; Power_W: 0.1; Value2: 0.1W; VDC_V: 75; TempCo: 100 ppm/C; SizeArea_mm2: 1.28; SizeX_mm: 1.6; SizeY_mm: 0.8; EIA_Code: E96; U/M: EA; AEC Category: Q200
R16 = CRCW06037M68FKEA: RES, 7.68 M, 1%, 0.1 W, 0603; Manufacturer: Vishay-Dale; CompType: Resistor; Value: 7.68Meg; Res_ohm: 7680000; Value_Code: 7M68; Tolerance_%: 1; Power_W: 0.1; Value2: 0.1W; VDC_V: 75; TempCo: 100 ppm/C; SizeArea_mm2: 1.28; SizeX_mm: 1.6; SizeY_mm: 0.8; EIA_Code: E96; U/M: EA; AEC Category: Q200
R17 = CRCW06034M42FKEA: RES, 4.42 M, 1%, 0.1 W, 0603; Manufacturer: Vishay-Dale; CompType: Resistor; Value: 4.42Meg; Res_ohm: 4420000; Value_Code: 4M42; Tolerance_%: 1; Power_W: 0.1; Value2: 0.1W; VDC_V: 75; TempCo: 100 ppm/C; SizeArea_mm2: 1.28; SizeX_mm: 1.6; SizeY_mm: 0.8; EIA_Code: E96; U/M: EA; AEC Category: Q200
R18 = CRCW06038M25FKEA: RES, 8.25 M, 1%, 0.1 W, 0603; Manufacturer: Vishay-Dale; CompType: Resistor; Value: 8.25Meg; Res_ohm: 8250000; Value_Code: 8M25; Tolerance_%: 1; Power_W: 0.1; Value2: 0.1W; VDC_V: 75; TempCo: 100 ppm/C; SizeArea_mm2: 1.28; SizeX_mm: 1.6; SizeY_mm: 0.8; EIA_Code: E96; U/M: EA; AEC Category: Q200
R19 = CRCW06034M75FKEA: RES, 4.75 M, 1%, 0.1 W, 0603; Manufacturer: Vishay-Dale; CompType: Resistor; Value: 4.75Meg; Res_ohm: 4750000; Value_Code: 4M75; Tolerance_%: 1; Power_W: 0.1; Value2: 0.1W; VDC_V: 75; TempCo: 100 ppm/C; SizeArea_mm2: 1.28; SizeX_mm: 1.6; SizeY_mm: 0.8; EIA_Code: E96; U/M: EA; AEC Category: Q200
R21 = MCR03EZPJ000: RES, 0, 5%, 0.1 W, 0603; Manufacturer: Rohm; CompType: Resistor; Value: 0; Value_Code: 0000; Tolerance_%: 5; Power_W: 0.1; Value2: 0.1W; TempCo: ppm/C; SizeArea_mm2: 1.28; SizeX_mm: 1.6; SizeY_mm: 0.8; SizeZ_mm: 1; EIA_Code: E24; U/M: EA; AEC Category: Q200; AEC Qualified: N
R23 = CRCW060310R0FKEA: as R22 on sheet TIDA-00649E2_DiodeVoltage
SH-J2 SH-J6 SH-J12 SH-J20 SH-J25 = 60900213421: as SH-J1 on sheet TIDA-00649E2_DiodeVoltage
SW_BOOST SW_BUCK = TESTPOINT_PIGTAIL: PIGTAIL; Manufacturer: Texas Instruments; SymbolCreator: Altium
U2 = BQ25570RGRR: Ultra Low Power Harvester Power Management IC with Boost Charger, and Nano-Powered Buck Converter, RGR0020A; Alternate PartNumber: BQ25570RGRT; Manufacturer: Texas Instruments; SymbolCreator: a0412235; SizeArea_mm2: 12.25; SizeAreaWB_mm2: 20.25; SizeX_mm: 3.5; SizeZ_mm: 1; U/M: EA
U3 = TS5A3160DBVR: 1-Ohm SPDT ANALOG SWITCH 5-V/3.3-V SINGLE-CHANNEL 2:1 MULTIPLEXER/DEMULTIPLEXER, DBV0006A; Alternate PartNumber: TS5A3160DBVT; Manufacturer: Texas Instruments; SymbolCreator: Altium; SizeArea_mm2: 8.12; SizeAreaWB_mm2: 14.82; SizeX_mm: 2.8; SizeY_mm: 2.9; SizeZ_mm: 1.45; CompType: IC; U/M: EA

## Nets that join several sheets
3V3: TIDA-00649E2_DiodeVoltage (J1.2 J5.1 J5.2), TIDA-00649E2_Boost (J24.3 J24.4 R21.2 U3.1)
GND: TIDA-00649E2_DiodeVoltage (14 pins), TIDA-00649E2_Boost (36 pins)
VBAT_OK: TIDA-00649E2_DiodeVoltage (J8.2), TIDA-00649E2_Boost (J11.2 J13.2 U2.13 U3.6)
V_Filter_Out: TIDA-00649E2_DiodeVoltage (R4.2), TIDA-00649E2_Boost (J6.1)

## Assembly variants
001: not fitted C2 C17 FID1 FID2 FID3 R21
